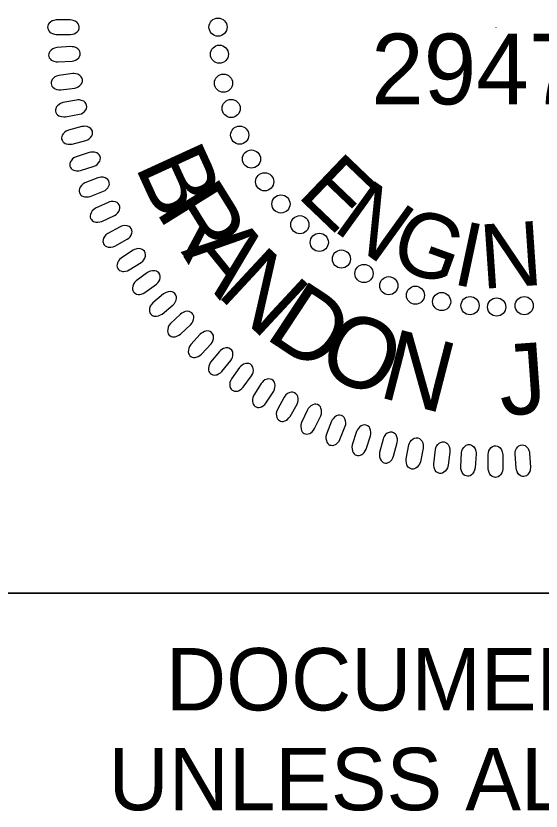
# Model space of a CAD drawing. Extents: x 505602 to 507286, y 483109 to 484209.
# Drawn here: x 507076.9 to 507123.2, y 484026.9 to 484097.1 of the extents above; entities that cross this region are included whole.
import ezdxf

# ---------------------------------------------------------------- set-up
doc = ezdxf.new("R2010")
doc.units = 0
for name, color, linetype in [('Sheet PE Seal Cell', 7, 'Continuous'), ('Sheet Profile CELL', 7, 'Continuous'), ('Sheet Sticker Exception Certification CELL', 7, 'Continuous')]:
    doc.layers.add(name, color=color, linetype=linetype)

msp = doc.modelspace()

# ---------------------------------------------------------------- linework, layer by layer
at = {"layer": 'Sheet PE Seal Cell'}
msp.add_line((507119.206, 484096.038), (507119.206, 484095.991), dxfattribs=at)
for points in [[(507081.659, 484096.701), (507080.432, 484096.701), (507080.213, 484096.663), (507080.073, 484096.612), (507079.904, 484096.499), (507079.794, 484096.402), (507079.714, 484096.29), (507079.674, 484096.186), (507079.654, 484096.073), (507079.674, 484095.962), (507079.704, 484095.842), (507079.763, 484095.737), (507079.864, 484095.632), (507079.943, 484095.572), (507080.093, 484095.505), (507080.273, 484095.445), (507080.432, 484095.423), (507081.689, 484095.415), (507081.858, 484095.437), (507081.998, 484095.482), (507082.157, 484095.572), (507082.297, 484095.684), (507082.377, 484095.781), (507082.437, 484095.938), (507082.457, 484096.088), (507082.416, 484096.237), (507082.367, 484096.341), (507082.268, 484096.469), (507082.098, 484096.589), (507081.918, 484096.656), (507081.789, 484096.686)], [(507081.712, 484094.343), (507080.487, 484094.267), (507080.271, 484094.215), (507080.134, 484094.155), (507079.972, 484094.032), (507079.868, 484093.928), (507079.796, 484093.811), (507079.763, 484093.705), (507079.75, 484093.591), (507079.777, 484093.481), (507079.815, 484093.363), (507079.88, 484093.262), (507079.987, 484093.164), (507080.07, 484093.109), (507080.223, 484093.052), (507080.406, 484093.003), (507080.566, 484092.991), (507081.822, 484093.062), (507081.99, 484093.095), (507082.126, 484093.149), (507082.279, 484093.248), (507082.412, 484093.369), (507082.486, 484093.47), (507082.536, 484093.631), (507082.546, 484093.781), (507082.497, 484093.928), (507082.44, 484094.03), (507082.333, 484094.15), (507082.157, 484094.259), (507081.973, 484094.315), (507081.842, 484094.336)], [(507081.876, 484091.962), (507080.659, 484091.809), (507080.446, 484091.744), (507080.314, 484091.675), (507080.16, 484091.542), (507080.063, 484091.432), (507079.998, 484091.311), (507079.972, 484091.202), (507079.966, 484091.088), (507080, 484090.98), (507080.044, 484090.865), (507080.116, 484090.768), (507080.229, 484090.677), (507080.316, 484090.627), (507080.472, 484090.579), (507080.658, 484090.543), (507080.819, 484090.54), (507082.067, 484090.69), (507082.232, 484090.733), (507082.365, 484090.796), (507082.512, 484090.904), (507082.636, 484091.033), (507082.704, 484091.139), (507082.743, 484091.303), (507082.744, 484091.453), (507082.686, 484091.597), (507082.623, 484091.694), (507082.509, 484091.808), (507082.326, 484091.905), (507082.139, 484091.949), (507082.007, 484091.963)], [(507082.21, 484089.636), (507081.004, 484089.407), (507080.796, 484089.329), (507080.669, 484089.252), (507080.523, 484089.11), (507080.433, 484088.994), (507080.376, 484088.869), (507080.356, 484088.759), (507080.358, 484088.645), (507080.398, 484088.539), (507080.45, 484088.427), (507080.528, 484088.335), (507080.646, 484088.251), (507080.735, 484088.207), (507080.895, 484088.169), (507081.083, 484088.144), (507081.243, 484088.151), (507082.479, 484088.379), (507082.642, 484088.433), (507082.771, 484088.503), (507082.91, 484088.621), (507083.027, 484088.757), (507083.087, 484088.868), (507083.116, 484089.033), (507083.108, 484089.184), (507083.041, 484089.323), (507082.972, 484089.417), (507082.85, 484089.523), (507082.662, 484089.608), (507082.472, 484089.641), (507082.34, 484089.646)], [(507082.689, 484087.295), (507081.501, 484086.991), (507081.298, 484086.9), (507081.175, 484086.815), (507081.039, 484086.664), (507080.957, 484086.542), (507080.907, 484086.414), (507080.895, 484086.303), (507080.903, 484086.189), (507080.95, 484086.086), (507081.009, 484085.978), (507081.093, 484085.891), (507081.216, 484085.814), (507081.308, 484085.776), (507081.469, 484085.748), (507081.658, 484085.735), (507081.818, 484085.753), (507083.037, 484086.057), (507083.196, 484086.121), (507083.32, 484086.2), (507083.452, 484086.326), (507083.56, 484086.469), (507083.613, 484086.583), (507083.632, 484086.75), (507083.614, 484086.9), (507083.538, 484087.035), (507083.464, 484087.124), (507083.336, 484087.223), (507083.142, 484087.295), (507082.951, 484087.317), (507082.818, 484087.313)], [(507083.343, 484085.011), (507082.176, 484084.633), (507081.979, 484084.529), (507081.862, 484084.437), (507081.735, 484084.278), (507081.661, 484084.151), (507081.62, 484084.02), (507081.615, 484083.908), (507081.63, 484083.796), (507081.684, 484083.696), (507081.749, 484083.591), (507081.838, 484083.51), (507081.966, 484083.441), (507082.059, 484083.408), (507082.223, 484083.391), (507082.412, 484083.389), (507082.571, 484083.417), (507083.768, 484083.798), (507083.922, 484083.872), (507084.042, 484083.958), (507084.165, 484084.092), (507084.263, 484084.241), (507084.31, 484084.359), (507084.318, 484084.527), (507084.291, 484084.675), (507084.207, 484084.805), (507084.127, 484084.889), (507083.993, 484084.979), (507083.795, 484085.04), (507083.603, 484085.049), (507083.471, 484085.037)], [(507084.102, 484082.774), (507082.961, 484082.323), (507082.77, 484082.207), (507082.659, 484082.108), (507082.543, 484081.941), (507082.477, 484081.81), (507082.444, 484081.676), (507082.446, 484081.565), (507082.468, 484081.453), (507082.528, 484081.357), (507082.6, 484081.256), (507082.693, 484081.181), (507082.825, 484081.121), (507082.921, 484081.094), (507083.086, 484081.086), (507083.274, 484081.097), (507083.431, 484081.135), (507084.602, 484081.589), (507084.752, 484081.673), (507084.865, 484081.766), (507084.98, 484081.908), (507085.069, 484082.064), (507085.108, 484082.184), (507085.105, 484082.352), (507085.069, 484082.498), (507084.977, 484082.622), (507084.892, 484082.701), (507084.753, 484082.783), (507084.551, 484082.831), (507084.359, 484082.828), (507084.228, 484082.808)], [(507085.001, 484080.615), (507083.891, 484080.093), (507083.709, 484079.966), (507083.604, 484079.859), (507083.499, 484079.685), (507083.441, 484079.551), (507083.416, 484079.415), (507083.425, 484079.304), (507083.454, 484079.194), (507083.52, 484079.101), (507083.598, 484079.005), (507083.697, 484078.936), (507083.832, 484078.884), (507083.929, 484078.863), (507084.093, 484078.866), (507084.281, 484078.889), (507084.435, 484078.936), (507085.576, 484079.464), (507085.719, 484079.557), (507085.827, 484079.656), (507085.932, 484079.805), (507086.012, 484079.966), (507086.043, 484080.088), (507086.03, 484080.256), (507085.984, 484080.4), (507085.884, 484080.518), (507085.794, 484080.592), (507085.651, 484080.664), (507085.446, 484080.699), (507085.255, 484080.685), (507085.125, 484080.657)], [(507086.049, 484078.466), (507084.973, 484077.875), (507084.799, 484077.737), (507084.702, 484077.624), (507084.607, 484077.445), (507084.558, 484077.306), (507084.542, 484077.17), (507084.557, 484077.059), (507084.594, 484076.951), (507084.666, 484076.862), (507084.75, 484076.772), (507084.852, 484076.709), (507084.99, 484076.665), (507085.089, 484076.651), (507085.252, 484076.664), (507085.438, 484076.698), (507085.589, 484076.755), (507086.694, 484077.354), (507086.832, 484077.455), (507086.932, 484077.562), (507087.029, 484077.717), (507087.097, 484077.882), (507087.121, 484078.006), (507087.097, 484078.172), (507087.043, 484078.313), (507086.936, 484078.425), (507086.842, 484078.493), (507086.693, 484078.556), (507086.487, 484078.579), (507086.297, 484078.552), (507086.169, 484078.516)], [(507087.205, 484076.392), (507086.169, 484075.734), (507086.003, 484075.586), (507085.914, 484075.467), (507085.83, 484075.281), (507085.79, 484075.14), (507085.783, 484075.003), (507085.805, 484074.893), (507085.848, 484074.788), (507085.926, 484074.704), (507086.015, 484074.619), (507086.121, 484074.562), (507086.261, 484074.528), (507086.36, 484074.52), (507086.523, 484074.543), (507086.707, 484074.589), (507086.853, 484074.655), (507087.919, 484075.322), (507088.05, 484075.431), (507088.144, 484075.545), (507088.23, 484075.705), (507088.288, 484075.875), (507088.304, 484076), (507088.27, 484076.164), (507088.207, 484076.301), (507088.093, 484076.406), (507087.995, 484076.467), (507087.842, 484076.522), (507087.635, 484076.532), (507087.447, 484076.492), (507087.322, 484076.448)], [(507088.482, 484074.417), (507087.488, 484073.695), (507087.333, 484073.537), (507087.25, 484073.413), (507087.179, 484073.222), (507087.148, 484073.079), (507087.149, 484072.941), (507087.178, 484072.834), (507087.228, 484072.73), (507087.31, 484072.652), (507087.405, 484072.572), (507087.515, 484072.523), (507087.657, 484072.497), (507087.756, 484072.495), (507087.917, 484072.529), (507088.097, 484072.586), (507088.24, 484072.661), (507089.261, 484073.393), (507089.385, 484073.511), (507089.471, 484073.63), (507089.548, 484073.796), (507089.595, 484073.968), (507089.603, 484074.094), (507089.559, 484074.257), (507089.487, 484074.389), (507089.367, 484074.486), (507089.265, 484074.542), (507089.11, 484074.587), (507088.903, 484074.583), (507088.717, 484074.532), (507088.595, 484074.481)], [(507089.885, 484072.535), (507088.939, 484071.753), (507088.794, 484071.585), (507088.72, 484071.456), (507088.661, 484071.261), (507088.638, 484071.116), (507088.648, 484070.979), (507088.684, 484070.873), (507088.74, 484070.774), (507088.827, 484070.701), (507088.926, 484070.627), (507089.039, 484070.585), (507089.182, 484070.568), (507089.282, 484070.572), (507089.44, 484070.616), (507089.616, 484070.684), (507089.754, 484070.768), (507090.727, 484071.564), (507090.844, 484071.689), (507090.922, 484071.813), (507090.988, 484071.983), (507091.025, 484072.158), (507091.024, 484072.284), (507090.97, 484072.443), (507090.89, 484072.571), (507090.764, 484072.661), (507090.659, 484072.71), (507090.501, 484072.744), (507090.295, 484072.729), (507090.113, 484072.666), (507089.994, 484072.606)], [(507091.395, 484070.765), (507090.5, 484069.925), (507090.366, 484069.748), (507090.3, 484069.614), (507090.253, 484069.416), (507090.24, 484069.27), (507090.258, 484069.134), (507090.301, 484069.03), (507090.363, 484068.935), (507090.454, 484068.867), (507090.558, 484068.8), (507090.673, 484068.765), (507090.818, 484068.757), (507090.916, 484068.768), (507091.072, 484068.821), (507091.244, 484068.9), (507091.375, 484068.993), (507092.296, 484069.847), (507092.405, 484069.98), (507092.476, 484070.108), (507092.531, 484070.283), (507092.556, 484070.46), (507092.548, 484070.585), (507092.484, 484070.741), (507092.396, 484070.864), (507092.265, 484070.945), (507092.157, 484070.987), (507091.997, 484071.012), (507091.792, 484070.983), (507091.614, 484070.909), (507091.5, 484070.842)], [(507093.131, 484068.986), (507092.29, 484068.092), (507092.167, 484067.907), (507092.11, 484067.769), (507092.075, 484067.569), (507092.071, 484067.422), (507092.098, 484067.287), (507092.147, 484067.187), (507092.215, 484067.095), (507092.31, 484067.034), (507092.419, 484066.973), (507092.535, 484066.945), (507092.68, 484066.946), (507092.778, 484066.963), (507092.93, 484067.026), (507093.096, 484067.116), (507093.222, 484067.217), (507094.088, 484068.128), (507094.187, 484068.266), (507094.25, 484068.399), (507094.294, 484068.577), (507094.308, 484068.755), (507094.292, 484068.88), (507094.219, 484069.031), (507094.123, 484069.148), (507093.987, 484069.221), (507093.876, 484069.256), (507093.716, 484069.271), (507093.513, 484069.229), (507093.34, 484069.144), (507093.23, 484069.07)], [(507094.821, 484067.456), (507094.038, 484066.511), (507093.927, 484066.318), (507093.878, 484066.177), (507093.856, 484065.975), (507093.862, 484065.829), (507093.897, 484065.696), (507093.952, 484065.598), (507094.026, 484065.511), (507094.124, 484065.456), (507094.236, 484065.402), (507094.354, 484065.382), (507094.499, 484065.392), (507094.596, 484065.415), (507094.743, 484065.487), (507094.903, 484065.587), (507095.023, 484065.696), (507095.83, 484066.659), (507095.921, 484066.804), (507095.974, 484066.941), (507096.008, 484067.12), (507096.011, 484067.299), (507095.986, 484067.423), (507095.903, 484067.569), (507095.801, 484067.68), (507095.661, 484067.744), (507095.547, 484067.772), (507095.386, 484067.777), (507095.187, 484067.722), (507095.019, 484067.627), (507094.914, 484067.546)], [(507096.601, 484066.056), (507095.88, 484065.063), (507095.781, 484064.864), (507095.741, 484064.72), (507095.732, 484064.517), (507095.747, 484064.371), (507095.79, 484064.24), (507095.851, 484064.147), (507095.93, 484064.064), (507096.033, 484064.015), (507096.148, 484063.969), (507096.267, 484063.955), (507096.41, 484063.975), (507096.506, 484064.004), (507096.648, 484064.086), (507096.802, 484064.196), (507096.914, 484064.311), (507097.659, 484065.323), (507097.74, 484065.474), (507097.786, 484065.613), (507097.808, 484065.794), (507097.8, 484065.974), (507097.767, 484066.095), (507097.676, 484066.237), (507097.566, 484066.341), (507097.422, 484066.396), (507097.308, 484066.417), (507097.147, 484066.412), (507096.95, 484066.344), (507096.79, 484066.239), (507096.69, 484066.151)], [(507098.503, 484064.643), (507097.846, 484063.606), (507097.759, 484063.402), (507097.728, 484063.256), (507097.732, 484063.052), (507097.756, 484062.908), (507097.808, 484062.781), (507097.874, 484062.69), (507097.959, 484062.614), (507098.063, 484062.57), (507098.181, 484062.531), (507098.301, 484062.526), (507098.443, 484062.554), (507098.536, 484062.589), (507098.673, 484062.679), (507098.82, 484062.799), (507098.924, 484062.921), (507099.604, 484063.978), (507099.676, 484064.134), (507099.713, 484064.275), (507099.723, 484064.458), (507099.703, 484064.636), (507099.663, 484064.756), (507099.564, 484064.891), (507099.448, 484064.987), (507099.3, 484065.033), (507099.185, 484065.048), (507099.025, 484065.032), (507098.833, 484064.953), (507098.679, 484064.837), (507098.585, 484064.744)], [(507100.521, 484063.427), (507099.93, 484062.352), (507099.857, 484062.142), (507099.835, 484061.994), (507099.852, 484061.792), (507099.884, 484061.648), (507099.944, 484061.525), (507100.016, 484061.439), (507100.105, 484061.368), (507100.212, 484061.332), (507100.332, 484061.3), (507100.452, 484061.301), (507100.592, 484061.339), (507100.683, 484061.38), (507100.814, 484061.479), (507100.953, 484061.607), (507101.05, 484061.736), (507101.662, 484062.833), (507101.723, 484062.993), (507101.751, 484063.137), (507101.75, 484063.32), (507101.72, 484063.496), (507101.673, 484063.613), (507101.564, 484063.741), (507101.442, 484063.83), (507101.292, 484063.867), (507101.176, 484063.874), (507101.017, 484063.848), (507100.831, 484063.757), (507100.685, 484063.632), (507100.596, 484063.534)], [(507102.58, 484062.32), (507102.058, 484061.211), (507101.998, 484060.996), (507101.986, 484060.848), (507102.015, 484060.646), (507102.056, 484060.506), (507102.124, 484060.386), (507102.201, 484060.305), (507102.295, 484060.239), (507102.404, 484060.21), (507102.525, 484060.186), (507102.645, 484060.195), (507102.783, 484060.241), (507102.871, 484060.287), (507102.995, 484060.394), (507103.126, 484060.531), (507103.215, 484060.666), (507103.757, 484061.799), (507103.808, 484061.963), (507103.827, 484062.108), (507103.814, 484062.291), (507103.773, 484062.465), (507103.718, 484062.578), (507103.602, 484062.699), (507103.474, 484062.781), (507103.323, 484062.809), (507103.206, 484062.808), (507103.049, 484062.772), (507102.869, 484062.67), (507102.732, 484062.535), (507102.65, 484062.431)], [(507104.708, 484061.312), (507104.256, 484060.172), (507104.21, 484059.954), (507104.207, 484059.805), (507104.249, 484059.606), (507104.298, 484059.468), (507104.374, 484059.353), (507104.456, 484059.277), (507104.553, 484059.217), (507104.664, 484059.195), (507104.787, 484059.178), (507104.906, 484059.195), (507105.04, 484059.25), (507105.125, 484059.301), (507105.243, 484059.416), (507105.364, 484059.561), (507105.444, 484059.701), (507105.914, 484060.866), (507105.956, 484061.032), (507105.965, 484061.178), (507105.941, 484061.36), (507105.888, 484061.531), (507105.827, 484061.641), (507105.703, 484061.755), (507105.571, 484061.828), (507105.418, 484061.845), (507105.302, 484061.837), (507105.147, 484061.792), (507104.974, 484061.679), (507104.845, 484061.536), (507104.77, 484061.427)], [(507106.917, 484060.41), (507106.537, 484059.243), (507106.505, 484059.023), (507106.511, 484058.874), (507106.565, 484058.678), (507106.624, 484058.544), (507106.706, 484058.433), (507106.793, 484058.363), (507106.894, 484058.309), (507107.006, 484058.294), (507107.13, 484058.285), (507107.247, 484058.309), (507107.378, 484058.373), (507107.459, 484058.43), (507107.57, 484058.551), (507107.682, 484058.703), (507107.753, 484058.848), (507108.149, 484060.041), (507108.18, 484060.209), (507108.18, 484060.356), (507108.144, 484060.535), (507108.081, 484060.702), (507108.013, 484060.809), (507107.882, 484060.914), (507107.746, 484060.979), (507107.592, 484060.988), (507107.477, 484060.972), (507107.325, 484060.917), (507107.159, 484060.793), (507107.039, 484060.642), (507106.971, 484060.529)], [(507109.25, 484059.737), (507108.944, 484058.549), (507108.926, 484058.328), (507108.941, 484058.179), (507109.008, 484057.987), (507109.074, 484057.856), (507109.164, 484057.751), (507109.255, 484057.686), (507109.358, 484057.639), (507109.472, 484057.631), (507109.595, 484057.63), (507109.711, 484057.661), (507109.837, 484057.732), (507109.915, 484057.794), (507110.018, 484057.923), (507110.12, 484058.082), (507110.182, 484058.231), (507110.502, 484059.446), (507110.522, 484059.616), (507110.513, 484059.762), (507110.466, 484059.939), (507110.393, 484060.102), (507110.318, 484060.204), (507110.181, 484060.301), (507110.042, 484060.357), (507109.886, 484060.356), (507109.773, 484060.333), (507109.625, 484060.269), (507109.467, 484060.134), (507109.357, 484059.977), (507109.296, 484059.859)], [(507112.772, 484058.95), (507112.541, 484057.744), (507112.463, 484057.536), (507112.386, 484057.408), (507112.244, 484057.263), (507112.128, 484057.174), (507112.003, 484057.116), (507111.892, 484057.097), (507111.778, 484057.099), (507111.673, 484057.139), (507111.56, 484057.191), (507111.469, 484057.269), (507111.385, 484057.387), (507111.341, 484057.476), (507111.303, 484057.636), (507111.278, 484057.824), (507111.286, 484057.985), (507111.514, 484059.22), (507111.568, 484059.383), (507111.639, 484059.511), (507111.757, 484059.651), (507111.893, 484059.767), (507112.003, 484059.828), (507112.168, 484059.856), (507112.32, 484059.848), (507112.458, 484059.78), (507112.552, 484059.712), (507112.658, 484059.591), (507112.743, 484059.402), (507112.776, 484059.212), (507112.781, 484059.08)], [(507115.138, 484058.623), (507114.983, 484057.406), (507114.919, 484057.194), (507114.849, 484057.061), (507114.717, 484056.907), (507114.607, 484056.811), (507114.485, 484056.745), (507114.377, 484056.719), (507114.263, 484056.714), (507114.155, 484056.747), (507114.039, 484056.792), (507113.943, 484056.864), (507113.852, 484056.977), (507113.802, 484057.064), (507113.754, 484057.221), (507113.718, 484057.406), (507113.715, 484057.567), (507113.866, 484058.814), (507113.909, 484058.979), (507113.972, 484059.113), (507114.08, 484059.26), (507114.209, 484059.384), (507114.316, 484059.451), (507114.479, 484059.491), (507114.63, 484059.491), (507114.773, 484059.433), (507114.871, 484059.371), (507114.985, 484059.256), (507115.081, 484059.073), (507115.126, 484058.886), (507115.139, 484058.753)], [(507117.455, 484058.426), (507117.377, 484057.201), (507117.326, 484056.985), (507117.265, 484056.849), (507117.143, 484056.686), (507117.039, 484056.583), (507116.922, 484056.511), (507116.815, 484056.477), (507116.701, 484056.465), (507116.591, 484056.492), (507116.474, 484056.529), (507116.373, 484056.595), (507116.275, 484056.702), (507116.22, 484056.785), (507116.162, 484056.939), (507116.114, 484057.122), (507116.102, 484057.282), (507116.173, 484058.537), (507116.207, 484058.704), (507116.261, 484058.841), (507116.36, 484058.994), (507116.48, 484059.127), (507116.583, 484059.2), (507116.743, 484059.25), (507116.894, 484059.26), (507117.041, 484059.211), (507117.141, 484059.155), (507117.262, 484059.048), (507117.37, 484058.871), (507117.427, 484058.687), (507117.448, 484058.556)], [(507119.808, 484058.354), (507119.808, 484057.127), (507119.77, 484056.908), (507119.718, 484056.768), (507119.606, 484056.599), (507119.508, 484056.489), (507119.396, 484056.409), (507119.292, 484056.369), (507119.18, 484056.35), (507119.068, 484056.37), (507118.948, 484056.399), (507118.843, 484056.459), (507118.738, 484056.559), (507118.679, 484056.639), (507118.611, 484056.789), (507118.552, 484056.968), (507118.529, 484057.128), (507118.522, 484058.384), (507118.545, 484058.553), (507118.59, 484058.693), (507118.679, 484058.853), (507118.791, 484058.992), (507118.889, 484059.073), (507119.046, 484059.132), (507119.196, 484059.152), (507119.345, 484059.112), (507119.45, 484059.062), (507119.577, 484058.963), (507119.696, 484058.793), (507119.764, 484058.613), (507119.793, 484058.484)], [(507122.175, 484058.477), (507122.251, 484057.252), (507122.228, 484057.031), (507122.185, 484056.888), (507122.083, 484056.712), (507121.994, 484056.596), (507121.886, 484056.51), (507121.785, 484056.464), (507121.674, 484056.437), (507121.561, 484056.45), (507121.44, 484056.472), (507121.331, 484056.525), (507121.22, 484056.618), (507121.156, 484056.694), (507121.08, 484056.839), (507121.009, 484057.015), (507120.976, 484057.172), (507120.89, 484058.426), (507120.902, 484058.597), (507120.938, 484058.739), (507121.018, 484058.904), (507121.121, 484059.05), (507121.213, 484059.136), (507121.366, 484059.205), (507121.514, 484059.234), (507121.665, 484059.204), (507121.773, 484059.161), (507121.906, 484059.07), (507122.036, 484058.907), (507122.115, 484058.732), (507122.153, 484058.605)]]:
    msp.add_lwpolyline(points, close=True, dxfattribs=at)
for centre in [(507094.698, 484096.065), (507094.817, 484093.675), (507095.174, 484091.125), (507095.85, 484088.894), (507096.606, 484086.543), (507097.641, 484084.432), (507098.81, 484082.428), (507100.242, 484080.475), (507101.914, 484078.642), (507103.625, 484077.088), (507105.576, 484075.613), (507107.566, 484074.338), (507109.755, 484073.262), (507112.104, 484072.424), (507114.413, 484071.866), (507116.921, 484071.506), (507119.27, 484071.386), (507121.699, 484071.505)]:
    msp.add_circle(centre, 0.801, dxfattribs=at)
at = {"layer": 'Sheet Profile CELL'}
msp.add_lwpolyline([(507069.03, 484158.662), (507169.08, 484158.662), (507169.08, 484046.162), (507069.03, 484046.162)], close=True, dxfattribs=at)
at = {"layer": 'Sheet Sticker Exception Certification CELL'}
msp.add_line((507069.03, 484046.162), (507269.067, 484046.162), dxfattribs=at)
msp.add_line((507069.03, 484046.162), (507269.067, 484046.162), dxfattribs=at)

# ---------------------------------------------------------------- texts
at = {"layer": 'Sheet PE Seal Cell'}
for s, height, rotation, p in [('29470', 6.2363, 359.98136, (507108.193, 484089.253)), ('B', 6.236, 294.5897, (507087.323, 484083.815)), ('E', 5.669, 316.26559, (507101.563, 484081.193)), ('R', 6.236, 301.86473, (507089.134, 484079.858)), ('N', 5.669, 324.20538, (507104.698, 484078.238)), ('G', 5.669, 340.08498, (507109.592, 484075.139)), ('I', 5.669, 348.02477, (507115.221, 484073.45)), ('N', 5.669, 3.90437, (507117.974, 484072.977)), ('A', 6.236, 308.98157, (507091.377, 484076.24)), ('N', 6.236, 317.09274, (507094.456, 484072.492)), ('D', 6.236, 326.58243, (507098.686, 484068.711)), ('O', 6.236, 335.45066, (507103.152, 484065.853)), ('N', 6.236, 345.5505, (507108.704, 484063.481)), ('J', 6.236, 4.1457, (507119.655, 484061.789))]:
    msp.add_text(s, height=height, rotation=rotation, dxfattribs=at).set_placement(p)
at = {"layer": 'Sheet Sticker Exception Certification CELL'}
for s, p in [('DOCUMENT NOT CONSIDERED FINAL', (507090.101, 484035.816)), ('DOCUMENT NOT CONSIDERED FINAL', (507090.101, 484035.816)), ('UNLESS ALL SIGNATURES COMPLETED', (507085.03, 484027.016)), ('UNLESS ALL SIGNATURES COMPLETED', (507085.03, 484027.016))]:
    msp.add_text(s, height=5.5, dxfattribs=at).set_placement(p)

doc.saveas('drawing.dxf')
